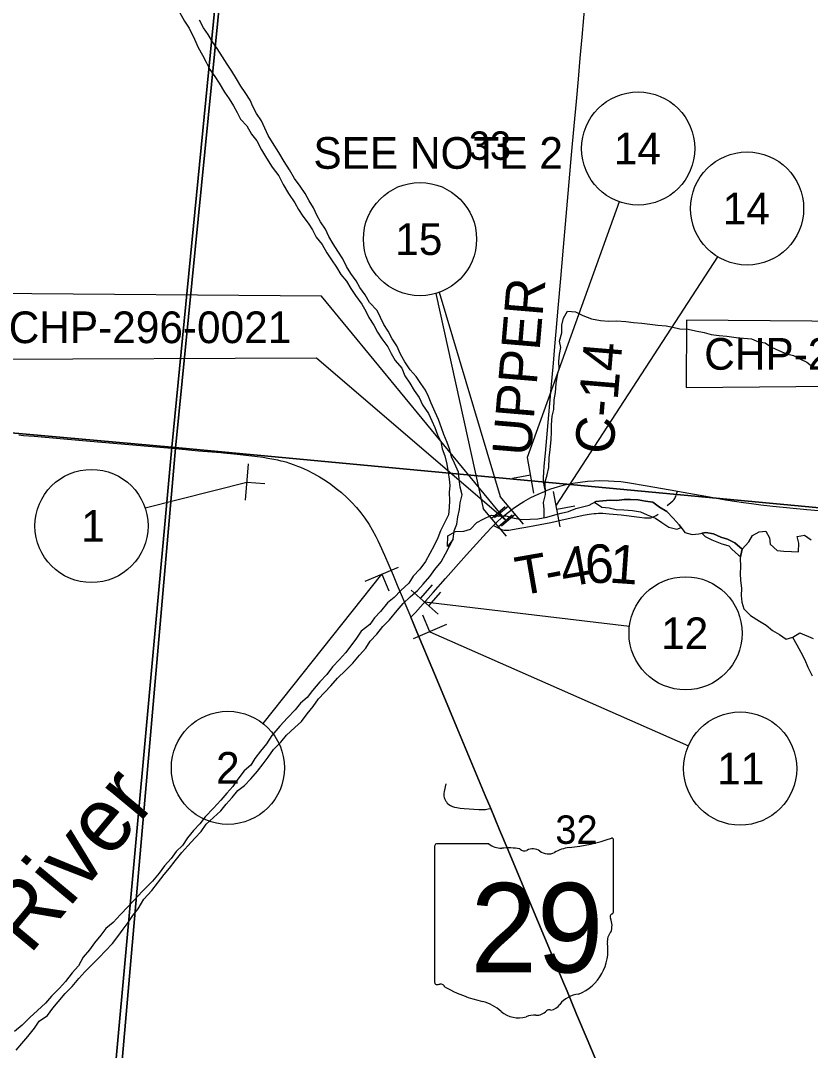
# Model space of a CAD drawing. Extents: x 0 to 1067, y 0 to 440.
# Drawn here: x 227.4 to 297.2, y 257.7 to 348.7 of the extents above; entities that cross this region are included whole.
import ezdxf

# ---------------------------------------------------------------- set-up
doc = ezdxf.new("R2010")
doc.units = 0
for name, color, linetype in [('Default', 7, 'Continuous'), ('GM_X_County_Road', 7, 'Continuous'), ('GM_X_County_Road_Text', 7, 'Continuous'), ('GM_X_Major_River', 7, 'Continuous'), ('GM_X_Major_River_Text', 7, 'Continuous'), ('GM_X_Minor_Lake', 7, 'Continuous'), ('GM_X_Minor_River', 7, 'Continuous'), ('GM_X_Section', 7, 'Continuous'), ('GM_X_Section_Text', 7, 'Continuous'), ('GM_X_State_Location', 7, 'Continuous'), ('GM_X_State_Route', 7, 'Continuous'), ('GM_X_State_Shield', 7, 'Continuous'), ('GM_X_Township_Road', 7, 'Continuous'), ('GM_X_Township_Road_Text', 7, 'Continuous'), ('SH_Masking', 7, 'Continuous'), ('SH_Text', 7, 'Continuous'), ('SN_P_Signs', 7, 'Continuous')]:
    doc.layers.add(name, color=color, linetype=linetype)

msp = doc.modelspace()

# ---------------------------------------------------------------- linework, layer by layer
at = {"layer": 'Default'}
msp.add_lwpolyline([(282.182, 247.372), (281.7, 248.521), (280.699, 250.931), (279.402, 254.066), (278.479, 256.266), (277.477, 258.675), (276.563, 260.878), (275.712, 262.904), (275.332, 263.795), (274.263, 266.416), (272.118, 271.491), (271.317, 273.458), (270.515, 275.383), (269.757, 277.167), (268.968, 279.051), (268.49, 280.193), (265.981, 286.215), (264.672, 289.345), (263.992, 290.96), (262.448, 294.662), (261.906, 295.947)], dxfattribs=at)
at = {"layer": 'GM_X_County_Road'}
msp.add_lwpolyline([(273.804, 307.111), (273.748, 307.334), (273.714, 307.472), (273.684, 307.615), (273.66, 307.792), (273.645, 307.999), (273.637, 308.276), (273.657, 308.769), (273.691, 309.3), (273.794, 310.449), (273.858, 311.118), (273.977, 312.492), (274.315, 316.205), (274.506, 318.397), (274.635, 319.882), (274.754, 321.22), (274.926, 323.263), (275.163, 325.899), (275.401, 328.649), (275.755, 332.734), (276.12, 336.819), (276.348, 339.382), (276.543, 341.535), (276.725, 343.503), (276.883, 345.361), (277.047, 347.217), (277.346, 350.653)], dxfattribs=at)
at = {"layer": 'GM_X_Major_River'}
for points in [[(241.454, 349.417), (241.886, 348.629), (242.323, 348.001), (242.773, 347.03), (243.116, 346.313), (243.484, 345.641), (243.807, 345.015), (244.129, 344.367), (244.589, 343.738), (244.959, 343.157), (245.437, 342.367), (245.851, 341.762), (246.22, 341.135), (246.544, 340.555), (246.846, 339.976), (247.398, 339.367), (247.832, 338.647), (248.293, 338.063), (248.702, 337.275), (249.135, 336.51), (249.658, 335.718), (250.229, 334.972), (250.616, 334.207), (251.093, 333.395), (251.661, 332.579), (251.985, 331.976), (252.355, 331.395), (252.838, 330.787), (253.207, 330.183), (253.53, 329.535), (254.057, 328.88), (254.491, 328.16), (254.883, 327.532), (255.343, 326.902), (255.71, 326.23), (256.217, 325.644), (256.607, 324.993), (257.022, 324.388), (257.569, 323.618), (257.915, 323.015), (258.194, 322.436), (258.63, 321.761), (258.954, 321.158), (259.346, 320.553), (259.872, 319.852), (260.173, 319.25), (260.52, 318.646), (261.115, 317.966), (261.368, 317.297), (261.804, 316.645), (262.195, 315.994), (262.633, 315.387), (262.932, 314.716), (263.456, 313.947), (263.756, 313.299), (264.012, 312.721), (264.266, 312.074), (264.545, 311.472), (264.685, 310.829), (264.918, 310.228), (265.079, 309.493), (265.194, 308.758), (265.29, 308.162), (265.365, 307.589), (265.301, 306.974), (265.326, 306.266), (265.285, 305.65), (265.221, 305.013)], [(265.659, 302.853), (265.749, 303.604), (265.971, 304.191), (266.058, 304.828), (266.214, 305.486), (266.253, 306.055), (266.456, 306.757), (266.271, 307.448), (266.178, 308.159), (266.128, 308.777), (265.764, 309.564), (265.508, 310.142), (265.343, 310.741), (265.112, 311.41), (264.836, 312.103), (264.626, 312.703), (264.351, 313.419), (264.052, 314.067), (263.711, 314.876), (263.454, 315.455), (263.198, 316.033), (262.783, 316.616), (262.391, 317.221), (261.839, 317.831), (261.381, 318.529), (260.991, 319.203), (260.672, 319.943), (260.257, 320.571), (259.913, 321.244), (259.52, 321.826), (258.919, 323.076), (258.257, 323.781), (257.867, 324.454), (257.407, 325.107), (257.06, 325.688), (256.601, 326.34), (256.209, 326.945), (255.887, 327.617), (255.452, 328.291), (255.038, 328.943), (254.671, 329.615), (254.348, 330.264), (253.934, 330.892), (253.61, 331.495), (253.288, 332.143), (252.918, 332.747), (252.573, 333.397), (252.137, 334.048), (251.633, 334.725), (251.177, 335.491), (250.698, 336.236), (250.243, 337.025), (249.677, 337.908), (249.308, 338.535), (248.709, 339.83), (248.25, 340.482), (247.949, 341.085), (247.693, 341.662), (247.256, 342.314), (246.864, 342.896), (246.495, 343.522), (246.083, 344.219), (245.668, 344.824), (245.255, 345.475), (244.798, 346.218), (244.36, 346.801), (243.992, 347.45), (243.577, 348.055), (243.233, 348.727)], [(265.221, 305.013), (264.906, 304.36), (264.519, 303.595), (264.297, 302.985), (263.957, 302.287), (263.573, 301.59), (263.187, 300.871), (262.69, 300.2), (262.125, 299.578), (261.72, 298.973), (261.018, 298.308), (260.431, 297.709), (259.848, 297.224), (259.233, 296.466), (258.693, 295.888), (258.266, 295.307), (257.52, 294.712), (257.044, 294.018), (256.121, 292.812), (255.603, 292.211), (254.992, 291.567), (254.494, 290.896), (253.861, 290.253), (253.2, 289.473), (252.727, 288.87), (252.143, 288.362), (251.671, 287.782), (251.013, 287.071), (250.33, 286.315), (249.624, 285.513), (249.146, 284.751), (248.604, 284.105), (248.13, 283.479), (247.748, 282.874), (247.164, 282.366), (246.619, 281.651), (246.168, 281.002), (245.626, 280.401), (245.108, 279.8), (244.472, 279.088), (243.721, 278.311), (243.248, 277.708), (242.684, 277.108), (242.164, 276.461), (241.735, 275.788), (241.15, 275.258), (240.722, 274.631), (240.134, 273.986), (239.66, 273.337), (239.069, 272.624), (238.155, 271.715), (237.497, 271.003), (236.886, 270.359), (236.228, 269.671), (235.593, 268.981), (234.94, 268.453), (234.49, 267.849), (233.947, 267.18), (233.496, 266.554), (232.953, 265.908), (232.521, 265.144), (231.979, 264.52), (231.388, 263.761), (230.847, 263.161), (230.144, 262.473), (229.602, 261.85), (228.9, 261.208), (228.221, 260.566), (227.541, 259.901), (226.865, 259.35)], [(227.022, 257.701), (227.517, 258.28), (228.059, 258.903), (228.627, 259.64), (229.054, 260.244), (229.797, 260.748), (230.249, 261.397), (230.721, 261.976), (231.357, 262.689), (231.967, 263.333), (232.557, 264.023), (233.075, 264.625), (233.755, 265.29), (234.342, 265.889), (234.905, 266.466), (235.539, 267.133), (236.012, 267.735), (236.464, 268.384), (236.913, 268.965), (237.342, 269.592), (237.814, 270.194), (238.317, 271.025), (239.023, 271.803), (239.497, 272.451), (240.111, 273.21), (240.584, 273.79), (241.081, 274.437), (241.671, 275.174), (242.189, 275.752), (242.801, 276.442), (243.365, 277.019), (243.816, 277.668), (244.471, 278.266), (245.103, 278.841), (245.575, 279.421), (246.116, 280.021), (246.613, 280.646), (247.195, 281.085), (247.758, 281.663), (248.347, 282.353), (248.844, 283.001), (249.294, 283.581), (249.769, 284.253), (250.426, 284.918), (250.922, 285.543), (251.648, 286.207), (252.232, 286.738), (252.753, 287.407), (253.273, 288.055), (253.748, 288.748), (254.829, 289.904), (255.418, 290.572), (256.144, 291.258), (256.778, 291.902), (257.368, 292.615), (257.932, 293.215), (258.314, 293.843), (258.902, 294.466), (259.422, 295.135), (260.009, 295.735), (260.693, 296.56), (261.235, 297.16), (261.844, 297.759), (262.498, 298.31), (262.993, 298.89), (263.582, 299.557), (264.033, 300.183), (264.576, 300.852), (264.96, 301.549), (265.659, 302.853)]]:
    msp.add_lwpolyline(points, dxfattribs=at)
at = {"layer": 'GM_X_Minor_Lake'}
for points in [[(285.794, 303.876), (285.618, 304.112), (285.09, 304.722), (284.538, 305.309), (283.889, 305.693), (283.309, 306.122), (282.652, 306.21), (281.994, 306.321), (281.335, 306.363), (280.766, 306.357), (280.126, 306.262), (279.512, 306.303), (278.872, 306.23), (278.256, 306.18), (278.137, 306.115)], [(278.137, 306.115), (278.788, 305.685), (279.447, 305.619), (280.057, 305.487), (280.739, 305.444), (281.489, 305.399), (282.214, 305.263), (282.799, 305.018), (283.518, 304.7), (284.099, 304.317), (284.724, 303.91), (285.425, 303.73), (285.794, 303.876)], [(291.18, 301.983), (290.558, 302.527), (289.908, 302.866), (289.299, 303.044), (288.669, 303.314), (287.99, 303.448), (287.64, 303.381)], [(287.64, 303.381), (287.927, 303.095), (288.519, 302.782), (288.808, 302.668), (289.11, 302.547), (289.406, 302.451), (289.719, 302.366), (290.021, 302.27), (290.293, 301.975), (290.582, 301.692), (290.872, 301.45), (291.048, 301.311)], [(291.048, 301.311), (291.18, 301.983)]]:
    msp.add_lwpolyline(points, dxfattribs=at)
at = {"layer": 'GM_X_Minor_River'}
for points in [[(273.686, 304.755), (273.704, 305.47), (273.631, 306.088), (273.812, 306.814), (273.776, 307.934), (273.954, 308.545), (274.109, 309.18), (274.134, 310.047), (274.224, 310.775), (274.317, 311.617), (274.338, 312.347), (274.333, 312.964), (274.401, 313.716), (274.555, 314.305), (274.58, 315.172), (274.69, 315.808), (274.759, 316.605), (274.871, 317.332), (275.025, 317.944), (274.998, 318.561), (275.039, 319.177), (275.171, 319.789), (275.051, 320.363), (275.254, 321.088), (275.251, 321.773), (275.406, 322.385), (275.742, 322.991), (276.47, 322.947), (277.098, 322.632), (277.863, 322.335), (278.678, 322.174), (279.406, 322.13), (280.112, 322.155), (280.907, 322.086), (281.588, 321.997), (282.315, 321.953), (283.041, 321.863), (283.744, 321.774), (284.471, 321.706), (285.059, 321.575), (285.67, 321.443), (286.42, 321.421), (287.076, 321.264), (287.823, 321.105), (288.456, 320.95), (289.159, 320.86), (289.84, 320.795), (290.657, 320.679), (291.315, 320.614), (292.02, 320.57), (292.626, 320.301), (293.215, 320.192), (293.796, 319.81), (294.426, 319.54), (295.1, 319.246), (295.733, 319.091), (296.338, 318.753), (296.922, 318.485), (297.545, 317.987)], [(265.659, 302.853), (265.139, 302.206), (265.166, 303.142), (265.861, 303.532), (266.59, 303.556), (267.165, 303.745), (267.728, 304.322), (268.306, 304.624), (269.022, 304.969), (269.68, 304.881), (270.295, 304.908), (271.041, 304.703), (271.743, 304.591), (272.45, 304.616), (273.134, 304.642), (273.913, 304.801), (274.624, 305.008), (275.198, 305.151), (275.839, 305.292), (276.485, 305.57), (277.081, 305.712), (277.655, 305.855), (278.256, 306.18), (278.872, 306.23), (279.512, 306.303), (280.126, 306.262), (280.766, 306.357), (281.335, 306.363), (281.994, 306.321), (282.652, 306.21), (283.309, 306.122), (283.889, 305.693), (284.538, 305.309), (285.09, 304.722), (285.618, 304.112), (286.122, 303.435), (286.778, 303.278), (287.372, 303.329), (287.99, 303.448), (288.669, 303.314), (289.299, 303.044), (289.908, 302.866), (290.558, 302.527), (291.18, 301.983), (291.768, 302.605), (292.103, 303.189), (292.682, 303.515), (293.276, 303.566), (293.623, 302.984), (293.675, 302.412), (294.295, 301.845), (294.886, 301.805), (295.568, 301.762), (296.16, 301.744), (296.204, 302.497), (296.062, 303.095), (296.703, 303.213), (297.306, 302.806)], [(291.18, 301.983), (291.02, 301.166), (291.044, 300.434), (291.025, 299.795), (291.031, 299.224), (291.124, 298.49), (291.106, 297.874), (291.157, 297.278), (291.345, 296.702), (291.942, 296.113), (292.724, 295.61), (293.306, 295.25), (293.884, 294.776), (294.489, 294.439), (295.068, 294.01), (295.666, 294.198), (296.292, 294.568), (297.461, 294.076)], [(295.643, 294.191), (296.033, 293.502), (296.379, 292.875), (296.723, 292.179), (297, 291.554), (297.387, 290.766)]]:
    msp.add_lwpolyline(points, dxfattribs=at)
at = {"layer": 'GM_X_Section'}
for points in [[(185.99, 376.405), (246.65, 370.913), (240.782, 310.986), (180.984, 316.33)], [(308.5, 365.904), (302.416, 305.207), (240.782, 310.986), (246.65, 370.913)], [(180.984, 316.33), (240.782, 310.986), (235.406, 252.097), (175.453, 257.739)], [(240.782, 310.986), (302.416, 305.207), (297.822, 243.897), (235.406, 252.097)]]:
    msp.add_lwpolyline(points, close=True, dxfattribs=at)
at = {"layer": 'GM_X_State_Route'}
for points in [[(227.25, 312.068), (227.659, 312.025), (228.597, 311.945), (232.88, 311.581), (238.674, 311.072), (241.117, 310.852)], [(241.117, 310.852), (243.128, 310.671), (245.097, 310.502), (245.332, 310.479)], [(245.332, 310.479), (246.564, 310.359), (247.843, 310.224), (248.843, 310.09), (249.275, 310.018), (249.801, 309.923), (250.108, 309.861), (250.422, 309.785), (250.611, 309.737), (250.856, 309.673), (251.178, 309.57), (251.602, 309.423), (251.874, 309.318), (252.159, 309.203), (252.466, 309.067), (252.744, 308.938), (253.309, 308.657), (253.831, 308.364), (254.37, 308.025), (254.832, 307.706), (255.309, 307.344), (255.772, 306.963), (256.244, 306.535), (256.669, 306.114), (257.096, 305.641), (257.476, 305.179), (257.836, 304.699), (258.21, 304.139), (258.482, 303.691), (258.808, 303.102), (258.998, 302.734), (259.174, 302.365), (259.589, 301.446), (260.348, 299.661), (260.707, 298.801), (261.721, 296.371), (261.906, 295.947)], [(261.906, 295.947), (262.305, 296.364), (263.888, 298.147), (264.982, 299.369), (266.829, 301.468), (268.579, 303.406), (269.041, 303.894), (269.207, 304.058), (269.441, 304.288), (270.021, 304.817), (270.536, 305.252), (270.952, 305.571), (271.415, 305.889), (271.894, 306.184), (272.518, 306.525), (273.157, 306.837), (273.707, 307.075), (273.804, 307.111), (274.267, 307.287), (274.873, 307.484), (275.489, 307.644), (276.222, 307.796), (276.887, 307.903), (277.519, 307.976), (278.117, 308.017), (278.604, 308.029), (279.389, 308.017), (279.892, 307.985), (280.471, 307.938), (281.064, 307.858), (282.795, 307.577), (285.33, 307.13), (285.467, 307.105), (287.968, 306.644), (289.731, 306.342), (291.315, 306.097), (292.026, 305.993), (292.854, 305.894), (293.902, 305.774), (296.907, 305.48), (300.323, 305.175)], [(261.906, 295.947), (262.448, 294.662), (263.992, 290.96), (264.672, 289.345), (265.981, 286.215), (268.49, 280.193), (268.968, 279.051), (269.757, 277.167), (270.515, 275.383), (271.317, 273.458), (272.118, 271.491), (274.263, 266.416), (275.332, 263.795), (275.712, 262.904), (276.563, 260.878), (277.477, 258.675), (278.479, 256.266), (279.402, 254.066), (280.699, 250.931), (281.7, 248.521), (282.182, 247.372)]]:
    msp.add_lwpolyline(points, dxfattribs=at)
at = {"layer": 'GM_X_State_Shield'}
for p, q in [((268.797, 275.925), (264.164, 275.925)), ((279.829, 269.941), (279.829, 276.222)), ((264.009, 275.718), (264.009, 263.711)), ((279.827, 269.943), (279.829, 269.941))]:
    msp.add_line(p, q, dxfattribs=at)
for centre, radius, start, end in [((264.19, 275.744), 0.183, 98.1301, 188.1301), ((269.901, 277.319), 1.778, 231.61951, 271.11188), ((274.193, 292.295), 16.777, 275.84447, 288.90645), ((279.653, 276.248), 0.176, 351.86209, 97.738), ((270.49, 269.184), 6.382, 80.48669, 94.98827), ((271.939, 275.806), 0.513, 219.79206, 297.10237), ((272.692, 274.418), 1.066, 54.46668, 119.14113), ((274.068, 276.322), 1.283, 233.85621, 294.82819), ((276.333, 272.257), 3.375, 97.34618, 120.76885), ((279.788, 269.48), 0.273, 107.94398, 210.33697), ((279.641, 269.917), 0.188, 289.60381, 7.73413), ((278.054, 268.686), 1.636, 340.03296, 23.64957), ((280.46, 267.313), 1.19, 136.8065, 186.92959), ((275.133, 266.514), 4.196, 292.30889, 8.98584), ((264.192, 263.685), 0.185, 171.95839, 258.30661), ((264.22, 264.913), 1.411, 267.33899, 280.60386), ((264.508, 263.018), 0.509, 29.74838, 93.27175), ((270.932, 273.806), 12.115, 240.41292, 257.1985), ((276.903, 260.34), 2.298, 94.40312, 142.57675), ((267.32, 258.317), 3.791, 47.18416, 75.83597), ((274.145, 260.897), 0.361, 65.75173, 132.64842), ((273.991, 262.547), 1.356, 282.87319, 323.27711), ((271.42, 262.959), 2.405, 230.70037, 286.29184), ((272.81, 258.807), 1.976, 85.69512, 111.20995), ((272.985, 262.059), 1.282, 268.77702, 315.54927)]:
    msp.add_arc(centre, radius, start, end, dxfattribs=at)
at = {"layer": 'GM_X_Township_Road'}
for points in [[(226.039, 191.956), (227.488, 191.835), (229.789, 191.625), (230.694, 191.542), (241.104, 310.884), (247.729, 377.873), (252.4, 425.107), (131, 425.107)], [(539, 425.107), (252.4, 425.107), (247.729, 377.873), (241.104, 310.884), (230.694, 191.542)], [(284.571, 305.824), (284.896, 306.081), (285.066, 306.229), (285.127, 306.288), (285.189, 306.37), (285.245, 306.456), (285.284, 306.532), (285.324, 306.619), (285.368, 306.742), (285.412, 306.905), (285.467, 307.105)], [(269.207, 304.058), (269.563, 303.878), (269.748, 303.784), (269.908, 303.715), (270.05, 303.671), (270.159, 303.65), (270.261, 303.641), (270.381, 303.642), (270.566, 303.661), (270.751, 303.684), (271.229, 303.765), (272.405, 303.975), (274.272, 304.34), (275.546, 304.617), (276.237, 304.774), (277.148, 304.973), (277.661, 305.066), (277.886, 305.096), (278.105, 305.121), (278.295, 305.135), (278.482, 305.145), (278.665, 305.145), (278.887, 305.139), (279.148, 305.125), (279.445, 305.104), (280.484, 304.999), (282.111, 304.792), (282.554, 304.738), (282.814, 304.726), (282.941, 304.731), (283.037, 304.74), (283.119, 304.751), (283.219, 304.775), (283.36, 304.823), (283.484, 304.884), (283.592, 304.942), (283.777, 305.067)], [(264.992, 281.239), (264.858, 280.547), (264.832, 280.381), (264.817, 280.256), (264.832, 280.129), (264.859, 280.028), (264.893, 279.928), (264.925, 279.866), (264.951, 279.804), (265.013, 279.69), (265.05, 279.635), (265.125, 279.528), (265.253, 279.409), (265.409, 279.315), (265.577, 279.239), (265.753, 279.182), (265.971, 279.133), (266.264, 279.091), (266.631, 279.058), (267.914, 278.965), (268.263, 278.956), (268.515, 278.97), (268.742, 279.01), (268.968, 279.051)]]:
    msp.add_lwpolyline(points, dxfattribs=at)
at = {"layer": 'SH_Masking'}
for centre in [(282.003, 337.379), (291.628, 332.075), (262.716, 329.369), (233.678, 304.018), (286.191, 294.535), (245.735, 282.643), (291.016, 282.579)]:
    msp.add_circle(centre, 5, dxfattribs=at)
at = {"layer": 'SH_Text'}
for p, q in [((280.326, 332.668), (272.201, 310.072)), ((289.009, 327.816), (274.751, 305.852)), ((264.115, 324.569), (268.301, 305.573)), ((264.423, 324.67), (269.803, 306.637)), ((238.417, 305.614), (247.397, 307.905)), ((248.847, 286.556), (259.347, 299.758)), ((281.226, 295.128), (263.128, 297.291)), ((263.592, 294.675), (286.441, 284.597))]:
    msp.add_line(p, q, dxfattribs=at)
for points in [[(270.306, 304.543), (254.006, 324.33), (224.715, 324.575), (224.812, 318.764), (253.556, 318.883)], [(330.109, 302.729), (315.812, 321.98), (286.28, 322.208), (286.245, 316.252), (315.363, 316.534)]]:
    msp.add_lwpolyline(points, close=True, dxfattribs=at)
for centre in [(282.003, 337.379), (291.628, 332.075), (262.716, 329.369), (233.678, 304.018), (286.191, 294.535), (245.735, 282.643), (291.016, 282.579)]:
    msp.add_circle(centre, 5, dxfattribs=at)
at = {"layer": 'SN_P_Signs'}
for p, q in [((247.537, 309.499), (247.257, 306.312)), ((272.201, 310.072), (272.756, 306.921)), ((247.397, 307.905), (248.991, 307.766)), ((272.478, 308.496), (270.903, 308.219)), ((275.112, 303.931), (274.522, 307.076)), ((271.866, 304.192), (269.803, 306.637)), ((274.817, 305.503), (276.389, 305.798)), ((270.365, 303.127), (268.301, 305.573)), ((269.024, 304.717), (270.246, 305.749)), ((270.525, 305.781), (269.302, 304.75)), ((269.643, 303.983), (270.865, 305.015)), ((271.144, 305.048), (269.921, 304.016)), ((270.834, 305.415), (270.834, 305.415)), ((270.834, 305.415), (270.834, 305.415)), ((269.333, 304.35), (269.333, 304.35)), ((269.333, 304.35), (269.333, 304.35)), ((257.87, 299.142), (260.823, 300.374)), ((259.347, 299.758), (259.963, 298.281)), ((262.769, 297.61), (263.832, 298.806)), ((261.932, 298.354), (264.325, 296.229)), ((263.487, 296.972), (264.55, 298.169)), ((263.128, 297.291), (263.128, 297.291)), ((263.128, 297.291), (263.128, 297.291)), ((263.592, 294.675), (262.97, 296.149)), ((265.066, 295.297), (262.118, 294.053))]:
    msp.add_line(p, q, dxfattribs=at)

# ---------------------------------------------------------------- texts
at = {"layer": 'GM_X_County_Road_Text'}
for s, rotation, p in [('UPPER', 85.16293, (272.491, 310.127)), ('C-14', 85.20824, (279.782, 310.284))]:
    msp.add_text(s, height=3.4091, rotation=rotation, dxfattribs=at).set_placement(p)
at = {"layer": 'GM_X_Major_River_Text'}
msp.add_text('River', height=5.6799, rotation=50.21475, dxfattribs=at).set_placement((228.199, 266.028))
at = {"layer": 'GM_X_Section_Text'}
for s, p in [('33', (267.029, 336.376)), ('32', (274.679, 275.926))]:
    msp.add_text(s, height=2.5114, rotation=0.00001, dxfattribs=at).set_placement(p)
at = {"layer": 'GM_X_State_Location'}
for s, p in [('s', (271.741, 268.916)), ('r', (271.74, 268.916))]:
    msp.add_text(s, height=0.0114, dxfattribs=at).set_placement(p)
msp.add_text('29', height=0.0114, rotation=0.00001, dxfattribs=at).set_placement((268.879, 268.089))
at = {"layer": 'GM_X_State_Shield'}
msp.add_text('29', height=7.9102, dxfattribs=at).set_placement((267.166, 264.558))
at = {"layer": 'GM_X_Township_Road_Text'}
for s, rotation, p in [('4', 10.10656, (275.429, 298.563)), ('6', 2.81641, (277.383, 298.918)), ('1', 355.90104, (279.372, 299.023)), ('T', 9.8759, (271.487, 297.849)), ('-', 10.94748, (274.068, 298.299))]:
    msp.add_text(s, height=3.409, rotation=rotation, dxfattribs=at).set_placement(p)
at = {"layer": 'SH_Text'}
for s, p in [('14', (279.848, 335.979)), ('SEE NOTE 2', (253.293, 335.586)), ('14', (289.473, 330.675)), ('15', (260.528, 327.969)), ('CHP-296-0021', (226.36, 320.177)), ('CHP-296-0122', (287.841, 317.827)), ('1', (232.762, 302.618)), ('12', (284.028, 293.135)), ('2', (244.69, 281.243))]:
    msp.add_text(s, height=2.8, dxfattribs=at).set_placement(p)
msp.add_text('11', height=2.8, rotation=360, dxfattribs=at).set_placement((288.983, 281.179))

doc.saveas('drawing.dxf')
